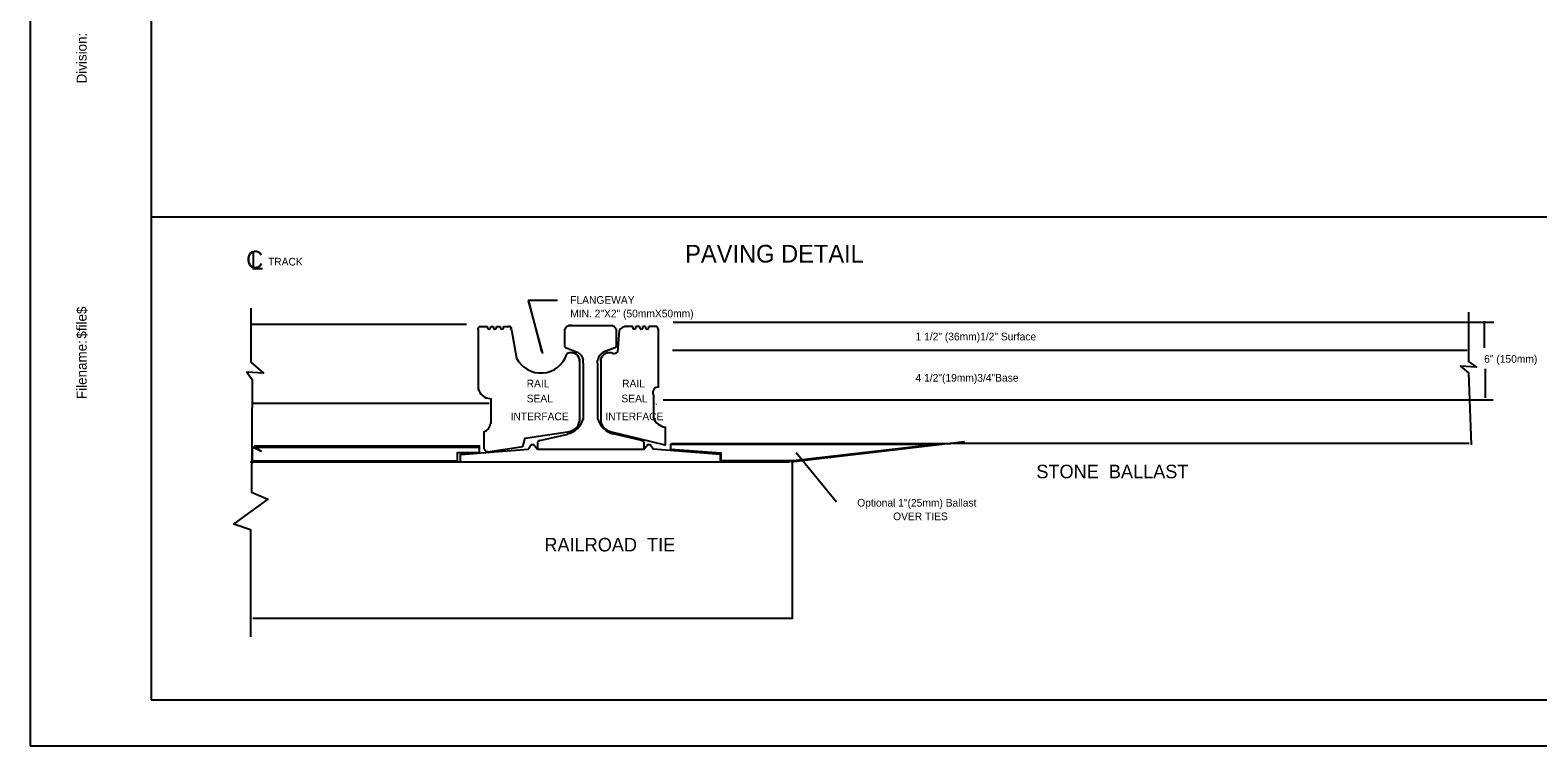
# Model space of a CAD drawing. Extents: x 1100953.69 to 1100956.55, y 386728.28 to 386730.11.
# Drawn here: x 1100953.692 to 1100955.371, y 386728.277 to 386729.073 of the extents above; entities that cross this region are included whole.
import ezdxf

# ---------------------------------------------------------------- set-up
doc = ezdxf.new("R2010")
doc.units = 0
for name, color, linetype in [('BORDER', 7, 'Continuous'), ('Level 1', 7, 'Continuous'), ('Level 33', 7, 'Continuous'), ('ORIG TOPO TEXT', 7, 'Continuous'), ('PLOT BOUNDARY', 7, 'Continuous')]:
    doc.layers.add(name, color=color, linetype=linetype)

msp = doc.modelspace()

# ---------------------------------------------------------------- linework, layer by layer
at = {"layer": 'BORDER'}
for p, q in [((1100953.8264, 386730.0776), (1100953.8264, 386728.3276)), ((1100953.8264, 386728.3276), (1100956.4931, 386728.3276))]:
    msp.add_line(p, q, dxfattribs=at)
at = {"layer": 'Level 1'}
for p, q in [((1100953.8264, 386728.8651), (1100955.4308, 386728.8651)), ((1100953.9372, 386728.7457), (1100954.1776, 386728.7457)), ((1100954.1904, 386728.7406), (1100954.1904, 386728.6725)), ((1100954.1919, 386728.7432), (1100954.2008, 386728.7432)), ((1100954.2008, 386728.7422), (1100954.2008, 386728.7432)), ((1100954.2044, 386728.7425), (1100954.2044, 386728.7432)), ((1100954.2044, 386728.7432), (1100954.2074, 386728.7432)), ((1100954.2074, 386728.7427), (1100954.2074, 386728.7432)), ((1100954.2109, 386728.7426), (1100954.2109, 386728.7432)), ((1100954.2109, 386728.7432), (1100954.2151, 386728.7432)), ((1100954.2151, 386728.7426), (1100954.2151, 386728.7432)), ((1100954.2187, 386728.7426), (1100954.2187, 386728.7432)), ((1100954.2187, 386728.7432), (1100954.2247, 386728.7432)), ((1100954.2275, 386728.7396), (1100954.2272, 386728.7406)), ((1100954.2275, 386728.7396), (1100954.2332, 386728.7081)), ((1100954.2868, 386728.7402), (1100954.2868, 386728.7209)), ((1100954.2949, 386728.7443), (1100954.2915, 386728.7443)), ((1100954.2919, 386728.7443), (1100954.3393, 386728.7443)), ((1100954.3385, 386728.7443), (1100954.3395, 386728.7443)), ((1100954.3441, 386728.7403), (1100954.3441, 386728.721)), ((1100954.3474, 386728.7387), (1100954.3457, 386728.7148)), ((1100954.3626, 386728.7432), (1100954.3565, 386728.7432)), ((1100954.3626, 386728.7426), (1100954.3626, 386728.7432)), ((1100954.3661, 386728.7426), (1100954.3661, 386728.7432)), ((1100954.3703, 386728.7432), (1100954.3661, 386728.7432)), ((1100954.3703, 386728.7426), (1100954.3703, 386728.7432)), ((1100954.3739, 386728.7427), (1100954.3739, 386728.7432)), ((1100954.3768, 386728.7432), (1100954.3739, 386728.7432)), ((1100954.3768, 386728.7425), (1100954.3768, 386728.7432)), ((1100954.3893, 386728.7432), (1100954.3804, 386728.7432)), ((1100954.3804, 386728.7422), (1100954.3804, 386728.7432)), ((1100954.3908, 386728.7403), (1100954.3908, 386728.6752)), ((1100954.4078, 386728.7479), (1100955.3215, 386728.7479)), ((1100955.3108, 386728.749), (1100955.3108, 386728.7195)), ((1100954.2889, 386728.7193), (1100954.3018, 386728.7143)), ((1100954.3427, 386728.7195), (1100954.3298, 386728.7145)), ((1100954.2892, 386728.7123), (1100954.2897, 386728.7131)), ((1100954.3034, 386728.7045), (1100954.3034, 386728.7074)), ((1100954.3034, 386728.7068), (1100954.3034, 386728.6377)), ((1100954.3075, 386728.7024), (1100954.3075, 386728.7058)), ((1100954.3075, 386728.7024), (1100954.3075, 386728.6399)), ((1100954.3235, 386728.7024), (1100954.3235, 386728.7058)), ((1100954.3235, 386728.7024), (1100954.3235, 386728.6401)), ((1100954.3269, 386728.7045), (1100954.3269, 386728.7074)), ((1100954.3269, 386728.7068), (1100954.3269, 386728.6377)), ((1100954.4069, 386728.7167), (1100955.2918, 386728.7167)), ((1100955.312, 386728.696), (1100955.312, 386728.6665)), ((1100953.939, 386728.6578), (1100954.2029, 386728.6578)), ((1100954.2047, 386728.6633), (1100954.2047, 386728.6348)), ((1100954.3856, 386728.6668), (1100954.3856, 386728.642)), ((1100955.3209, 386728.6612), (1100954.3966, 386728.6612)), ((1100954.1968, 386728.6262), (1100954.1968, 386728.6091)), ((1100954.2593, 386728.6162), (1100954.2902, 386728.6235)), ((1100954.3724, 386728.6162), (1100954.3409, 386728.6236)), ((1100953.9384, 386728.609), (1100954.1926, 386728.609)), ((1100954.2529, 386728.6112), (1100954.2566, 386728.6067)), ((1100954.3752, 386728.6135), (1100954.3752, 386728.6147)), ((1100954.3791, 386728.6112), (1100954.3754, 386728.6067)), ((1100954.4057, 386728.613), (1100954.7171, 386728.613)), ((1100954.5388, 386728.5926), (1100954.7321, 386728.6152)), ((1100955.2942, 386728.6132), (1100954.7188, 386728.6132)), ((1100953.9366, 386728.5926), (1100954.5373, 386728.5926))]:
    msp.add_line(p, q, dxfattribs=at)
for points in [[(1100953.9374, 386728.7637), (1100953.9374, 386728.7034), (1100953.9513, 386728.6913), (1100953.933, 386728.6924), (1100953.9387, 386728.6841), (1100953.938, 386728.5588), (1100953.9561, 386728.5509), (1100953.9182, 386728.5238), (1100953.9368, 386728.5172), (1100953.937, 386728.398)], [(1100955.2934, 386728.7593), (1100955.2934, 386728.7044), (1100955.3024, 386728.6978), (1100955.2843, 386728.699), (1100955.2934, 386728.6918), (1100955.2964, 386728.6116)], [(1100954.1904, 386728.7406), (1100954.1904, 386728.7406), (1100954.1904, 386728.7399), (1100954.1905, 386728.7418)], [(1100954.3908, 386728.7406), (1100954.3908, 386728.7406), (1100954.3908, 386728.7399), (1100954.3907, 386728.7418)], [(1100954.2013, 386728.6038), (1100954.2404, 386728.6096), (1100954.2428, 386728.6191), (1100954.2898, 386728.6259)], [(1100954.3989, 386728.6316), (1100954.3989, 386728.6111), (1100954.3378, 386728.6261)], [(1100954.1709, 386728.5927), (1100954.1709, 386728.6006), (1100954.2461, 386728.6067), (1100954.2492, 386728.6111)], [(1100954.2564, 386728.6147), (1100954.2564, 386728.6067), (1100954.3752, 386728.6067), (1100954.3752, 386728.6135)], [(1100954.4605, 386728.5927), (1100954.4605, 386728.6006), (1100954.3853, 386728.6067), (1100954.3823, 386728.6111)], [(1100954.5401, 386728.5936), (1100954.5401, 386728.4181), (1100953.9394, 386728.4181)]]:
    msp.add_lwpolyline(points, dxfattribs=at)
msp.add_lwpolyline([(1100954.2911, 386728.624), (1100954.2911, 386728.624)], close=True, dxfattribs=at)
for centre, radius, start, end in [((1100954.193, 386728.7407), 0.00272, 113.2296, 156.6511), ((1100954.2026, 386728.7422), 0.00183, 168.0862, 10.8769), ((1100954.2091, 386728.7422), 0.00183, 163.5969, 13.8929), ((1100954.2169, 386728.7422), 0.00183, 167.8619, 13.3346), ((1100954.2244, 386728.7405), 0.0028, 3.2783, 90), ((1100954.2249, 386728.7405), 0.0028, 0, 90), ((1100954.2249, 386728.7405), 0.0028, 0, 90), ((1100954.2249, 386728.7405), 0.0028, 0, 90), ((1100954.2249, 386728.7405), 0.0028, 0, 90), ((1100954.2249, 386728.7405), 0.0028, 0, 90), ((1100954.2249, 386728.7405), 0.0028, 0, 90), ((1100954.2249, 386728.7405), 0.0028, 0, 90), ((1100954.2249, 386728.7405), 0.0028, 0, 90), ((1100954.2249, 386728.7405), 0.0028, 0, 90), ((1100954.2249, 386728.7405), 0.0028, 0, 90), ((1100954.2937, 386728.7368), 0.00767, 102.9237, 153.7577), ((1100954.3373, 386728.7369), 0.00767, 26.2423, 74.3223), ((1100954.3555, 386728.7337), 0.00958, 84.0797, 148.5721), ((1100954.3563, 386728.7405), 0.0028, 90, 110.0189), ((1100954.3643, 386728.7422), 0.00183, 166.6654, 12.1381), ((1100954.3721, 386728.7422), 0.00183, 166.1071, 16.4031), ((1100954.3786, 386728.7422), 0.00183, 169.1231, 11.9138), ((1100954.3882, 386728.7407), 0.00272, 23.3489, 66.7704), ((1100954.2603, 386728.7218), 0.0304, 169.9505, 170.3663), ((1100954.289, 386728.7216), 0.00232, 198.5348, 271.2942), ((1100954.3419, 386728.7217), 0.00232, 268.7058, 341.4652), ((1100954.2603, 386728.7218), 0.0304, 206.6954, 341.8593), ((1100954.2939, 386728.7042), 0.00989, 15.59, 115.2679), ((1100954.2968, 386728.7045), 0.0109, 6.1354, 65.0971), ((1100954.3344, 386728.7046), 0.0109, 114.9029, 173.8646), ((1100954.3364, 386728.7042), 0.00989, 64.9947, 164.41), ((1100954.3414, 386728.7193), 0.00622, 262.5811, 313.5897), ((1100954.2047, 386728.6776), 0.0147, 193.3928, 266.186), ((1100954.3909, 386728.6697), 0.00603, 78.2184, 208.8447), ((1100954.4004, 386728.6467), 0.0155, 136.9197, 138.5844), ((1100954.1945, 386728.6354), 0.00953, 283.8405, 0), ((1100954.2889, 386728.6408), 0.0149, 273.5762, 347.9902), ((1100954.2846, 386728.647), 0.0239, 283.2999, 342.8148), ((1100954.2889, 386728.6408), 0.0149, 342.258, 344.0542), ((1100954.3465, 386728.647), 0.0239, 196.6797, 256.7001), ((1100954.3414, 386728.6408), 0.0149, 192.0097, 256.1884), ((1100954.3414, 386728.6408), 0.0149, 195.9458, 197.742), ((1100954.4004, 386728.6467), 0.0155, 197.6941, 265.3751), ((1100954.2015, 386728.6086), 0.00476, 173.0072, 270), ((1100954.2511, 386728.6085), 0.00319, 127.8554, 131.8354), ((1100954.2511, 386728.6085), 0.00319, 54.3431, 127.8554), ((1100954.2598, 386728.612), 0.00432, 94.1428, 141.1061), ((1100954.3717, 386728.612), 0.00432, 38.8939, 85.8572), ((1100954.3805, 386728.6085), 0.00319, 52.1446, 125.6569)]:
    msp.add_arc(centre, radius, start, end, dxfattribs=at)
at = {"layer": 'Level 33'}
for p, q in [((1100954.2461, 386728.7717), (1100954.2623, 386728.7133)), ((1100955.311, 386728.7287), (1100955.311, 386728.7467)), ((1100955.3119, 386728.6819), (1100955.3119, 386728.6639)), ((1100954.5897, 386728.5477), (1100954.5447, 386728.6026))]:
    msp.add_line(p, q, dxfattribs=at)
msp.add_lwpolyline([(1100954.2788, 386728.7722), (1100954.2467, 386728.7722), (1100954.2609, 386728.7153)], dxfattribs=at)
for points in [[(1100953.9411, 386728.6104), (1100954.1917, 386728.6104), (1100954.1917, 386728.6028), (1100954.167, 386728.6028), (1100954.167, 386728.5933), (1100953.9391, 386728.5933), (1100953.9391, 386728.6092), (1100953.9487, 386728.6046)], [(1100954.6883, 386728.612), (1100954.4045, 386728.612), (1100954.4045, 386728.6066), (1100954.4607, 386728.6025), (1100954.4607, 386728.5941), (1100954.5413, 386728.5941), (1100954.6936, 386728.6116), (1100954.6852, 386728.6116)]]:
    msp.add_lwpolyline(points, close=True, dxfattribs=at)
at = {"layer": 'PLOT BOUNDARY'}
msp.add_lwpolyline([(1100953.6916, 386728.2766), (1100956.5249, 386728.2766), (1100956.5249, 386730.1099), (1100953.6916, 386730.1099)], close=True, dxfattribs=at)

# ---------------------------------------------------------------- texts
at = {"layer": 'BORDER'}
for s, p in [('Division:', (1100953.7545, 386729.0137)), ('$file$', (1100953.7545, 386728.7297)), ('Filename:', (1100953.7545, 386728.6625))]:
    msp.add_text(s, height=0.01116, rotation=90, dxfattribs=at).set_placement(p)
at = {"layer": 'ORIG TOPO TEXT'}
for s, height, p in [('C', 0.0197, (1100953.9321, 386728.8079)), ('C', 0.0197, (1100953.9321, 386728.8079)), ('L', 0.0197, (1100953.9367, 386728.8065)), ('TRACK', 0.00853, (1100953.9564, 386728.8111)), ('PAVING DETAIL', 0.019685, (1100954.421, 386728.8144)), ('FLANGEWAY', 0.00853, (1100954.293, 386728.7685)), ('MIN. 2"X2" (50mmX50mm)', 0.008531, (1100954.293, 386728.7534)), ('1 1/2" (36mm)1/2" Surface', 0.008531, (1100954.6776, 386728.7278)), ('6" (150mm)', 0.00853, (1100955.3108, 386728.7029)), ('4 1/2"(19mm)3/4"Base', 0.008531, (1100954.6776, 386728.6819)), ('RAIL', 0.00853, (1100954.2445, 386728.6755)), ('RAIL', 0.00853, (1100954.3508, 386728.6755)), ('SEAL', 0.00853, (1100954.2445, 386728.6588)), ('SEAL', 0.00853, (1100954.35, 386728.6588)), ('INTERFACE', 0.00853, (1100954.2266, 386728.6389)), ('INTERFACE', 0.00853, (1100954.3321, 386728.6389)), ('STONE  BALLAST', 0.015091, (1100954.8121, 386728.5743)), ('Optional 1"(25mm) Ballast', 0.008531, (1100954.6126, 386728.5428)), ('OVER TIES', 0.00853, (1100954.6526, 386728.5277)), ('RAILROAD  TIE', 0.015091, (1100954.2642, 386728.4929))]:
    msp.add_text(s, height=height, dxfattribs=at).set_placement(p)

doc.saveas('drawing.dxf')
